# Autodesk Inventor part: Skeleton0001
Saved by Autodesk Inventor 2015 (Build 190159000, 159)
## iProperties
Created: 2020-03
Part Number: Skeleton0001
Material: 一般
Document SubType Name: Modeling
Designer: 徐冠倫
Density: 1 g/cm^3
Appearance: 預設
_SkeletonDoc: Frame Skeleton File
_Version: 15.0.0
Author: 徐冠倫
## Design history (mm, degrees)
node "Reference Skeleton"
